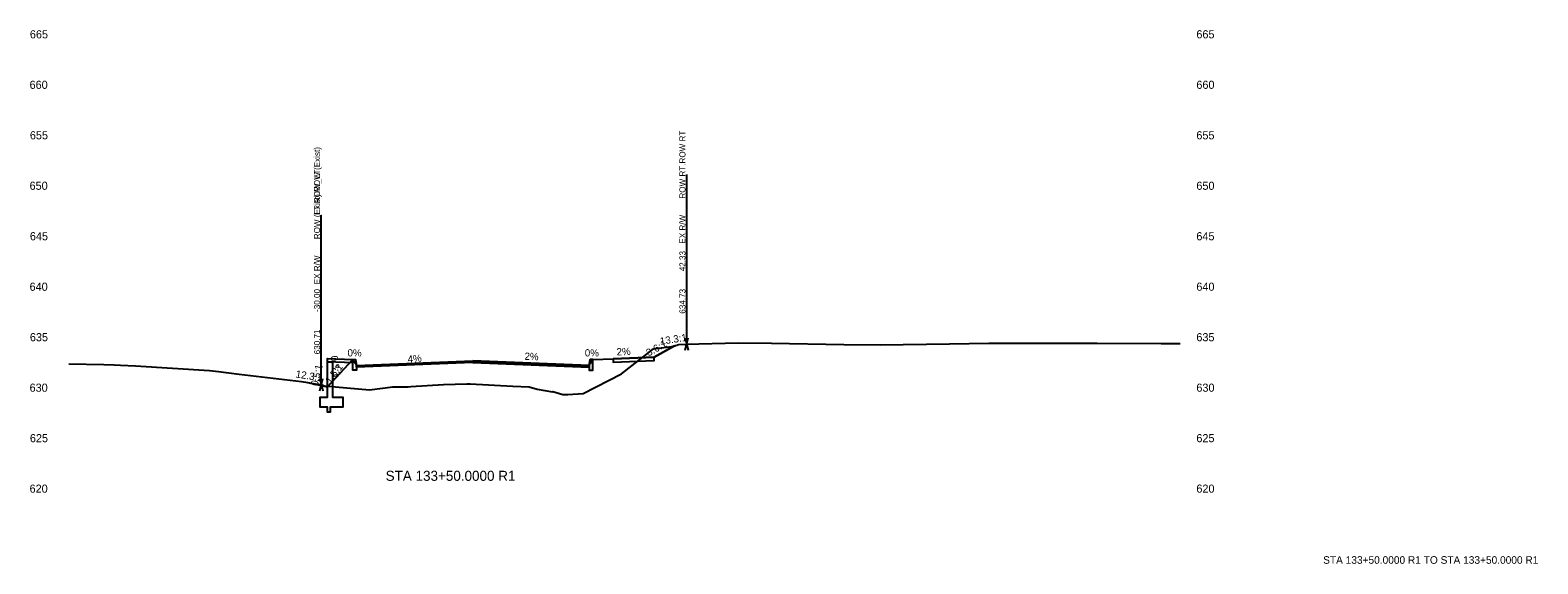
# Model space of a CAD drawing. Extents: x 2 to 741, y 16 to 2207.
# Drawn here: x 442.4 to 740.8, y 1140.9 to 1246.6 of the extents above; entities that cross this region are included whole.
import ezdxf

# ---------------------------------------------------------------- set-up
doc = ezdxf.new("R2010")
doc.units = 0
for name, color, linetype in [('BORD_text_large_2', 7, 'Continuous'), ('Draft_XS_Feature_Name', 7, 'Continuous'), ('Draft_XS_Label', 7, 'Continuous'), ('Draft_XS_Point_Label_Indicator', 7, 'Continuous'), ('Draft_XS_Terminator', 7, 'Continuous'), ('Draft_XS_Text', 7, 'Continuous'), ('E_ROW', 7, 'Continuous'), ('E_Terrain_Exterior', 7, 'Continuous'), ('E_Terrain_Points_Low', 7, 'Continuous'), ('Grade_Veg_Grass', 7, 'Continuous'), ('P_XS_Sections', 7, 'Continuous'), ('Road_Curb', 7, 'Continuous'), ('Road_Pave_Asphalt', 7, 'Continuous'), ('Road_Sidewalk', 7, 'Continuous'), ('Struc_Wall', 7, 'Continuous'), ('Terrain_Design', 7, 'Continuous')]:
    doc.layers.add(name, color=color, linetype=linetype)

msp = doc.modelspace()

# ---------------------------------------------------------------- linework, layer by layer
at = {"layer": 'Draft_XS_Terminator'}
for p, q in [((572.33, 1184.46), (572.33, 1206.46)), ((500, 1176.41), (500, 1198.41)), ((500, 1176.41), (500, 1198.41))]:
    msp.add_line(p, q, dxfattribs=at)
at = {"layer": 'E_ROW'}
for p, q in [((572.33, 1184.46), (572.33, 1218.06)), ((500, 1176.41), (500, 1210.01)), ((500, 1176.41), (500, 1210.01)), ((572.03, 1183.26), (572.63, 1185.66)), ((572.03, 1185.66), (572.63, 1183.26)), ((499.7, 1175.21), (500.3, 1177.61)), ((499.7, 1177.61), (500.3, 1175.21)), ((499.7, 1175.21), (500.3, 1177.61)), ((499.7, 1177.61), (500.3, 1175.21))]:
    msp.add_line(p, q, dxfattribs=at)
at = {"layer": 'E_Terrain_Exterior'}
msp.add_lwpolyline([(450, 1180.53), (456.96, 1180.4), (459.03, 1180.32), (460.25, 1180.28), (463.2, 1180.1), (477.89, 1179.21), (479.68, 1179), (481.17, 1178.82), (481.73, 1178.76), (483.76, 1178.51), (496.09, 1177), (497.31, 1176.85), (498.82, 1176.55), (499.5, 1176.48), (500.03, 1176.41), (500.55, 1176.17), (509.57, 1175.37), (514.17, 1175.96), (514.6, 1175.98), (517.22, 1176), (517.74, 1176.06), (524.2, 1176.43), (528.8, 1176.57), (529.02, 1176.56), (529.5, 1176.54), (537.89, 1176.13), (541.16, 1175.98), (542.74, 1175.54), (545.76, 1174.98), (545.84, 1175.02), (547.79, 1174.48), (548.81, 1174.48), (551.83, 1174.66), (559.45, 1178.56), (565.79, 1183.51), (569.35, 1183.94), (569.44, 1183.97), (569.5, 1183.98), (569.74, 1184.05), (569.77, 1184.06), (569.82, 1184.07), (569.91, 1184.1), (569.99, 1184.12), (570.12, 1184.15), (570.16, 1184.16), (570.46, 1184.25), (570.53, 1184.27), (570.78, 1184.34), (572.15, 1184.45), (582.53, 1184.7), (589.14, 1184.62), (603.46, 1184.34), (610.63, 1184.3), (624.38, 1184.46), (632.11, 1184.62), (645.31, 1184.65), (653.59, 1184.61), (666.24, 1184.56), (670, 1184.53)], dxfattribs=at)
at = {"layer": 'Grade_Veg_Grass'}
for points in [[(569.89, 1184.09), (565.89, 1181.87), (565.89, 1181.87)], [(553.75, 1181.39), (557.78, 1181.55)], [(497.25, 1176.86), (501.25, 1175.95), (501.25, 1175.95)]]:
    msp.add_lwpolyline(points, dxfattribs=at)
at = {"layer": 'Road_Curb'}
for points in [[(507, 1180.22), (507, 1179.3), (506.25, 1179.3), (506.25, 1181.39), (506.77, 1181.39), (507, 1180.22)], [(553, 1180.22), (553, 1179.3), (553.75, 1179.3), (553.75, 1181.39), (553.23, 1181.39), (553, 1180.22)]]:
    msp.add_lwpolyline(points, dxfattribs=at)
at = {"layer": 'Road_Pave_Asphalt'}
for points in [[(530, 1181.14), (530, 1180.81), (507, 1179.89), (507, 1180.22), (530, 1181.14)], [(530, 1181.14), (530, 1180.81), (553, 1179.89), (553, 1180.22), (530, 1181.14)]]:
    msp.add_lwpolyline(points, dxfattribs=at)
at = {"layer": 'Road_Sidewalk'}
for points in [[(557.78, 1181.55), (557.78, 1180.88), (565.89, 1181.21), (565.89, 1181.87), (557.78, 1181.55)], [(506.25, 1181.39), (506.25, 1180.72), (501.25, 1180.92), (501.25, 1181.59), (506.25, 1181.39)]]:
    msp.add_lwpolyline(points, dxfattribs=at)
at = {"layer": 'Struc_Wall'}
msp.add_lwpolyline([(501.25, 1173.95), (501.25, 1175.95), (501.25, 1175.95), (501.25, 1180.92), (502.25, 1180.88), (502.25, 1180.88), (502.25, 1173.95), (502.25, 1173.95), (504.25, 1173.95), (504.25, 1173.95), (504.25, 1171.95), (504.25, 1171.95), (504.25, 1171.95), (501.75, 1171.95), (501.75, 1170.95), (501.75, 1170.95), (501.25, 1170.95), (501.25, 1170.95), (501.25, 1170.95), (501.25, 1171.95), (501.25, 1171.95), (499.75, 1171.95), (499.75, 1171.95), (499.75, 1173.95), (501.25, 1173.95), (501.25, 1173.95), (501.25, 1173.95)], dxfattribs=at)
at = {"layer": 'Terrain_Design'}
for points in [[(497.25, 1176.86), (501.25, 1175.95), (506.25, 1181.39), (506.77, 1181.39), (507, 1180.22), (530, 1181.14), (553, 1180.22), (553.23, 1181.39), (553.75, 1181.39), (557.78, 1181.55), (565.89, 1181.87), (569.89, 1184.09)], [(501.25, 1181.59), (501.25, 1181.59), (506.25, 1181.39), (506.77, 1180.58), (507, 1180.22), (530, 1181.14), (553, 1180.22), (553.23, 1180.58), (553.75, 1181.39), (557.78, 1181.55), (565.89, 1181.87), (569.89, 1184.09)]]:
    msp.add_lwpolyline(points, dxfattribs=at)

# ---------------------------------------------------------------- texts
at = {"layer": 'BORD_text_large_2'}
msp.add_text('STA 133+50.0000 R1 TO STA 133+50.0000 R1', height=1.5, dxfattribs=at).set_placement((698.32, 1140.92))
at = {"layer": 'Draft_XS_Feature_Name'}
for s, p in [('ROW RT.ROW RT', (572.09, 1213.26)), ('ROW (Exist).ROW (Exist)', (499.76, 1205.21)), ('ROW_LT.ROW_LT', (499.76, 1205.21))]:
    msp.add_text(s, height=1.2, rotation=90, dxfattribs=at).set_placement(p)
at = {"layer": 'Draft_XS_Label'}
for s, p in [('42.33', (572.09, 1198.86)), ('-30.00', (499.76, 1190.81)), ('-30.00', (499.76, 1190.81)), ('634.73', (572.09, 1190.46)), ('630.71', (499.76, 1182.41)), ('630.71', (499.76, 1182.41))]:
    msp.add_text(s, height=1.2, rotation=90, dxfattribs=at).set_placement(p)
at = {"layer": 'Draft_XS_Point_Label_Indicator'}
for p in [(565.87, 1181.86), (569.87, 1184.08), (501.24, 1181.58), (506.24, 1181.38), (506.76, 1181.38), (506.99, 1180.21), (506.99, 1179.29), (552.99, 1180.21), (552.99, 1179.29), (553.22, 1181.38), (553.74, 1181.38), (557.77, 1181.54), (497.24, 1176.85), (502.16, 1175.93)]:
    msp.add_text('X', height=0.024, dxfattribs=at).set_placement(p)
at = {"layer": 'Draft_XS_Text'}
for s, height, p in [('665', 1.608, (442.32, 1245)), ('665', 1.608, (673.22, 1245)), ('660', 1.608, (442.26, 1235)), ('660', 1.608, (673.22, 1235)), ('655', 1.608, (442.32, 1225)), ('655', 1.608, (673.22, 1225)), ('650', 1.608, (442.26, 1215)), ('650', 1.608, (673.22, 1215)), ('645', 1.608, (442.32, 1205)), ('645', 1.608, (673.22, 1205)), ('640', 1.608, (442.26, 1195)), ('640', 1.608, (673.22, 1195)), ('635', 1.608, (442.32, 1185)), ('635', 1.608, (673.22, 1185)), ('630', 1.608, (442.26, 1175)), ('630', 1.608, (673.22, 1175)), ('625', 1.608, (442.32, 1165)), ('625', 1.608, (673.22, 1165)), ('STA 133+50.0000 R1', 1.992, (512.74, 1157.35)), ('620', 1.608, (442.26, 1155)), ('620', 1.608, (673.22, 1155))]:
    msp.add_text(s, height=height, dxfattribs=at).set_placement(p)
for s, rotation, p in [('3.6:1', 28.9919, (564.8, 1181.96)), ('13.3:1', 8.5526, (567.15, 1184.29)), ('0.3:1', 279.2259, (501.79, 1182.02)), ('0%', 360, (505.2, 1181.99)), ('4%', 4.5657, (517.14, 1180.72)), ('2%', 357.7094, (540.21, 1181.33)), ('0%', 360, (552.17, 1181.99)), ('2%', 2.2906, (558.48, 1182.18)), ('12.3:1', 350.7837, (494.86, 1177.85)), ('0.5:1', 76.4243, (499.29, 1176.03)), ('1.5:1', 53.1139, (501.81, 1176.47))]:
    msp.add_text(s, height=1.44, rotation=rotation, dxfattribs=at).set_placement(p)
at = {"layer": 'E_ROW'}
for p in [(572.09, 1204.34), (499.76, 1196.29), (499.76, 1196.29)]:
    msp.add_text('EX R/W', height=1.2, rotation=90, dxfattribs=at).set_placement(p)
at = {"layer": 'E_Terrain_Points_Low'}
msp.add_text('X', height=0.024, dxfattribs=at).set_placement((529.99, 1181.13))
at = {"layer": 'P_XS_Sections'}
msp.add_text('-', height=0.0001, dxfattribs=at).set_placement((450, 1155))

doc.saveas('drawing.dxf')
